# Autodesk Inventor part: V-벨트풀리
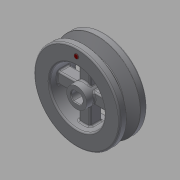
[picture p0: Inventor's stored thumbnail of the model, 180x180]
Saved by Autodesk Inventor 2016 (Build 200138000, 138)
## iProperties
Created: 2018-01
Part Number: V-벨트풀리
Material: 스테인리스강
Document SubType Name: Modeling
Designer: mduedu
Density: 8.08 g/cm^3
Appearance: 기본값
Mass: 218.724 g
Surface Area: 130.785 cm^2
Volume: 27.0698 cm^3
Author: mduedu
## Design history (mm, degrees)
sketch "스케치1"
  geometry: C1 r 30 at (0, 0); 1 further point
  constraints: 1 centre point, 1 coincident
  dimensions: "d0" = 60 diameter of C1
extrude "돌출1" new body sketch "스케치1" stored distance "d1" = 19; taper "d2" = 0 deg
sketch "스케치2"
  geometry: L1 (30, -9.5)-(-30, -9.5) reference; L2 (-30, -9.5)-(-30, 9.5) reference; L3 (-30, 9.5)-(30, 9.5) reference; L4 (30, 9.5)-(30, -9.5) reference; L5 (-30, 0)-(30, 0); L6 (30, 4.825)-(21, 2.074); L7 (21, 2.074)-(21, -2.074); L8 (21, -2.074)-(30, -4.825); L9 (30, -4.825)-(30, 4.825); L10 (27.3, 9.5)-(27.3, -9.5); L11 (0, -13.3)-(0, 13.3) reference; 4 further points
  constraints: 12 end point, 9 point on line, 3 midpoint, 2 perpendicular, 1 collinear, 1 symmetric about line
  dimensions: "d3" = 34 deg angle of L8 L6; "d4" = 2.7 distance between parallel lines of L10 L4; "d5" = 6.3 distance between parallel lines of L7 L10; "d6" = 8 distance of point (27.3, -4) point (27.3, 4)
revolve "회전1" sketch "스케치2" stored, may be unused: angle "d7" = 90 deg
fillet "모깎기1" dims "d8" = 0.2
fillet "모깎기2" dims "d9" = 0.5
fillet "모깎기3" dims "d10" = 1
sketch "스케치3"
  geometry: C1 r 19 at (0, 0); 1 further point
  constraints: 1 centre point, 1 coincident
  dimensions: "d11" = 38 diameter of C1
extrude "돌출2" cut sketch "스케치3" stored distance "d12" = 19; taper "d13" = 0 deg
sketch "스케치4"
  geometry: C1 r 7 at (0, 0); 1 further point
  constraints: 1 centre point, 1 coincident
  dimensions: "d14" = 14 diameter of C1
extrude "돌출3" join sketch "스케치4" stored distance "d15" = 19; taper "d16" = 0 deg
sketch "스케치5"
  geometry: L1 (0, 7)-(0, 19); L2 (4, 5.745)-(4, 18.574); L3 (-4, 5.745)-(-4, 18.574); C1 r 21 at (0, 0) reference; A1 r 19 centre (0, 0) between (0, 19) and (-4, 18.574) reference; A2 r 7 centre (0, 0) between (0, 7) and (-4, 5.745) reference; 1 further point
  constraints: 6 end point, 6 point on circle, 2 parallel, 1 point on line, 1 vertical, 1 other
  dimensions: "d17" = 8 distance between parallel lines of L2 L3
extrude "돌출4" join sketch "스케치5" stored distance "d18" = 8; taper "d19" = 0 deg
fillet "모깎기4" dims "d20" = 1
fillet "모깎기5" dims "d24" = 1
fillet "모깎기6" dims "d25" = 1
hole "구멍1" diameter "d28" = 8; stored, may be unused: countersink angle "d32" = 90 deg, drill point angle "d34" = 118 deg; dims "d26" = 10, "d27" = 10, "d29" = 6, "d30" = 4, "d31" = 2, "d33" = 8
sketch "스케치6"
  geometry: L1 (-2.332, -3.25)-(2.332, -3.25); L2 (2.332, 3.25)-(-2.332, 3.25); L3 (-2.332, -3.25)-(2.332, 3.25); L4 (2.332, -3.25)-(-2.332, 3.25); A1 r 4 centre (0, 0) between (2.332, 3.25) and (-2.332, 3.25) reference; A2 r 4 centre (0, 0) between (2.332, 3.25) and (-2.332, 3.25); A3 r 4 centre (0, 0) between (-2.332, -3.25) and (2.332, -3.25); 1 further point
  constraints: 8 end point, 7 point on circle, 2 centre point, 2 coincident, 2 midpoint, 1 horizontal, 1 parallel
  dimensions: "d35" = 6.5 distance of L1.end L2.start
extrude "돌출5" join sketch "스케치6" stored distance "d37" = 8; taper "d38" = 0 deg
chamfer "모따기1" distance "d39" = 0.5; stored, may be unused: second distance "d40" = 2, angle "d41" = 45 deg
chamfer "모따기2" distance "d42" = 0.5; stored, may be unused: second distance "d43" = 2, angle "d44" = 45 deg
sketch "스케치7" dims "d45" = 50
  geometry: C1 r 1.5 at (0, 25); 2 further points
  constraints: 2 vertical alignment, 1 centre point, 1 coincident, 2 other
  dimensions: "d46" = 3 diameter of C1
extrude "돌출6" join sketch "스케치7" distance "d47" = 0.5; taper "d48" = 0 deg
fillet "모깎기7" dims "d49" = 0.1
node "솔리드1"
pattern_circular "원형 패턴1" dims angle "d22" = 360 deg
node "절단 모서리 투영1"
node "절단 모서리 투영2"
